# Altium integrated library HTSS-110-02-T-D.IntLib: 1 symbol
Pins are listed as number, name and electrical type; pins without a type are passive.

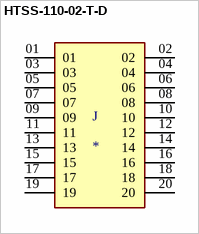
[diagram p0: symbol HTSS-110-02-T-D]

## HTSS-110-02-T-D
designator J
Connector Header Through Hole 20 position 0.100 (2.54mm); MF: Samtec; MP: HTSS-110-02-T-D
footprint SAMTEC_HTSS-110-02-T-D
pins: 01, 02, 03, 04, 05, 06, 07, 08, 09, 10, 11, 12, 13, 14, 15, 16, 17, 18, 19, 20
